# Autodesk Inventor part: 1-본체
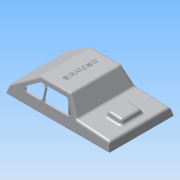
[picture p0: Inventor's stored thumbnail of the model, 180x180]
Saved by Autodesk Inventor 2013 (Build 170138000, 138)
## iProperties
Created: 2015-05
Part Number: 1-본체
Material: ABS 플라스틱
Document SubType Name: Modeling
Designer: Administrator
Density: 1.06 g/cm^3
Mass: 31.5653 g
Surface Area: 297.913 cm^2
Volume: 29.7786 cm^3
Author: Administrator
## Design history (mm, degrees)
sketch "스케치1"
  geometry: L1 (61, -38)-(-61, -38); L2 (-61, -38)-(-61, 38); L3 (-61, 38)-(61, 38); L4 (61, 38)-(61, -38); L5 (61, -38)-(-61, 38); L6 (-61, -38)-(61, 38); 1 further point
  constraints: 12 end point, 2 midpoint, 2 parallel, 1 horizontal, 1 perpendicular
  dimensions: "d0" = 122 distance of L2.end L3.end; "d2" = 76 distance of L3.end L1.start
extrude "돌출1" new body sketch "스케치1" distance "d3" = 30; taper "d4" = -15 deg
node "작업 평면1"
sketch "스케치3"
  geometry: L1 (52.962, 30)-(-52.962, 30) reference; L2 (-61, 0)-(-52.962, 30) reference; L3 (61, 0)-(-61, 0) reference; L4 (61, 0)-(52.962, 30) reference; L5 (-58.588, 9)-(-19, 11.075); L6 (-19, 11.075)-(-7.174, 30); L7 (28.321, 30)-(58.321, 10); L8 (60.732, 1)-(59.732, 1); L9 (59.732, 1)-(59.732, 0); L10 (-60.732, 1)-(-59.732, 1); L11 (-59.732, 1)-(-59.732, 0); L12 (61, 0)-(52.962, 30) reference; 1 further point
  constraints: 14 end point, 8 point on line, 3 perpendicular, 1 parallel
  dimensions: "d23" = 9 distance from line of L3 L5.start; "d25" = 125 deg angle of L6 L5; "d27" = 1 distance of L10.start L10.end; "d28" = 1 distance of L10.end L11.end; "d29" = 1 distance of L8.start L8.end; "d30" = 1 distance of L8.end L9.end; "d31" = 30 horizontal distance of L7.start L7.end; "d32" = 20 vertical distance of L7.start L7.end; "d34" = 3 deg angle of L3 L5; "d83" = 42 horizontal distance of L5.end L2.start
extrude "돌출3" cut sketch "스케치3" stored distance "d35" = 31; taper "d36" = 0 deg
sketch "스케치5"
  geometry: L1 (-8.121, 22.588)-(-28.121, 22.588); L2 (-28.121, 22.588)-(-28.121, 48.588); L3 (-28.121, 48.588)-(-8.121, 48.588); L4 (-8.121, 48.588)-(-8.121, 22.588); L5 (-8.121, 22.588)-(-28.121, 48.588); L6 (-28.121, 22.588)-(-8.121, 48.588); L7 (2.879, 73.588)-(2.879, -2.412) reference; 3 further points
  constraints: 12 end point, 3 midpoint, 2 parallel, 1 horizontal, 1 horizontal alignment, 1 perpendicular
  dimensions: "d37" = 20 distance of L2.end L3.end; "d40" = 26 distance of L1.end L2.end; "d65" = 11 distance between parallel lines of L7 L4
extrude "돌출4" join sketch "스케치5" distance "d42" = 5; taper "d43" = -20 deg
feature "쉘1" dims "d44" = 2
sketch "스케치6"
  geometry: L1 (-4.403, 25)-(-10.908, 14.59); L2 (-8.364, 10)-(17.224, 10); L3 (20.224, 13)-(20.224, 22); L4 (17.224, 25)-(-4.403, 25); L5 (61, 0)-(58.321, 10) reference; L6 (58.321, 10)-(28.321, 30) reference; L7 (28.321, 30)-(-7.174, 30) reference; L8 (-7.174, 30)-(-19, 11.075) reference; L9 (-19, 11.075)-(-58.588, 9) reference; L10 (-61, 0)-(-58.588, 9) reference; L11 (61, 0)-(-61, 0) reference; L12 (-7.174, 30)-(-19, 11.075) reference; L13 (58.321, 10)-(28.321, 30) reference; L14 (21.307, 22)-(21.307, 13); L15 (24.307, 10)-(39.398, 10); L16 (41.062, 15.496)-(26.807, 25); L17 (26.807, 25)-(24.307, 25); A1 r 3 centre (39.398, 13) between (39.398, 10) and (41.062, 15.496); A2 r 3 centre (24.307, 22) between (24.307, 25) and (21.307, 22); A3 r 3 centre (24.307, 13) between (21.307, 13) and (24.307, 10); A4 r 3 centre (17.224, 22) between (20.224, 22) and (17.224, 25); A5 r 3 centre (17.224, 13) between (17.224, 10) and (20.224, 13); A6 r 3 centre (-8.364, 13) between (-10.908, 14.59) and (-8.364, 10); 6 further points
  constraints: 16 end point, 12 point on circle, 12 tangent, 10 point on line, 6 centre point, 4 equal radius, 4 perpendicular, 3 parallel, 2 collinear, 1 horizontal
  dimensions: "d46" = 34 distance of point (-13.776, 10) point (20.224, 10); "d48" = 15 vertical distance of L1.start point (-13.776, 10); "d54" = 5 distance between parallel lines of L8 L1; "d56" = 5 distance between parallel lines of L4 L7; "d79" = 5 distance between parallel lines of L6 L16; "d80" = 28 distance of point (21.307, 10) point (49.307, 10); "d81" = 3 radius of A1; "d82" = 3 radius of A2
extrude "돌출5" cut sketch "스케치6" stored distance "d57" = 5; taper "d58" = 0 deg
sketch "스케치10"
  geometry: L1 (61, -38)-(61, 38) reference; L2 (61, 38)-(-61, 38) reference; L3 (-61, 38)-(-61, -38) reference; L4 (-60, -37)-(-60, 37); L5 (-60, 37)-(60, 37); L6 (60, 37)-(60, -37); L7 (-60, -37)-(60, -37); L8 (-61, -38)-(61, -38) reference; 1 further point
  constraints: 8 end point, 1 perpendicular
  dimensions: "d66" = 1 distance between parallel lines of L2 L5; "d67" = 1 distance between parallel lines of L8 L7; "d68" = 1 distance between parallel lines of L4 L3; "d69" = 1 distance between parallel lines of L1 L6
extrude "돌출6" join sketch "스케치10" distance "d70" = 1; taper "d71" = 0 deg
sketch "스케치11"
  geometry: L1 (-60, 37)-(-60, -37) reference; L2 (-60, -37)-(60, -37) reference; L3 (60, -37)-(60, 37) reference; L4 (60, 37)-(-60, 37) reference; L5 (-59, 36)-(-59, -36); L6 (-59, -36)-(59, -36); L7 (59, -36)-(59, 36); L8 (59, 36)-(-59, 36); 1 further point
  constraints: 8 end point, 3 other
  dimensions: "d72" = 1 distance between parallel lines of L8 L4
extrude "돌출7" cut sketch "스케치11" distance "d73" = 1; taper "d74" = 0 deg
node "작업 평면2"
sketch "스케치12"
  geometry: L1 (-33.879, -9.78)-(-33.879, 9.78) reference; L2 (-33.879, 9.78)-(-47.42, 9.78) reference; L3 (-47.42, 9.78)-(-47.42, -9.78) reference; L4 (-47.42, -9.78)-(-33.879, -9.78) reference; C1 r 3 at (-40.65, 0); C2 r 3 at (-0.65, -22); C3 r 3 at (-0.65, 22); C4 r 3 at (39.35, 0); 3 further points
  constraints: 4 centre point, 3 equal radius, 2 horizontal alignment, 2 midpoint, 2 vertical alignment
  dimensions: "d85" = 40 horizontal distance of C3.centre C1.centre; "d87" = 40 horizontal distance of C4.centre C3.centre; "d89" = 6 diameter of C4; "d90" = 22 vertical distance of point (0, 0) C3.centre; "d91" = 22 vertical distance of point (0, 0) C2.centre
extrude "돌출8" join sketch "스케치12" stored distance "d92" = 1; taper "d93" = 0 deg
sketch "스케치15"
  geometry: L1 (-61, -38)-(-61, 38) reference; 2 further points
  constraints: 1 horizontal alignment, 1 other
  dimensions: "d103" = 50 distance from line of L1 point (-11, 0)
feature "엠보싱1" sketch "스케치15" dims "d0" = 122, "d2" = 76, "d104" = 0.5, "d105" = 0
fillet "모깎기1" dims "d101" = 3
fillet "모깎기2" dims "d102" = 3
fillet "모깎기4" dims "d107" = 3
fillet "모깎기5" dims "d108" = 3
fillet "모깎기6" dims "d109" = 3
fillet "모깎기7" dims "d110" = 12
fillet "모깎기10" dims "d113" = 3
fillet "모깎기11" dims "d114" = 3
sketch "스케치16"
  geometry: C1 r 3 at (0, 0) reference; C2 r 3 at (-80, 0) reference; C3 r 3 at (-40, 22) reference; C4 r 3 at (-40, -22) reference; 5 further points
  constraints: 4 coincident
hole "구멍1" sketch "스케치16" at (0, 0), (-40, 22), (-40, -22), (-80, 0) diameter "d115" = 3.242; stored, may be unused: countersink angle "d119" = 90 deg, drill point angle "d121" = 118 deg; dims "d116" = 9, "d117" = 4, "d118" = 2, "d120" = 11
node "솔리드1"
node "투영된 루프1"
node "투영된 루프2"
node "투영된 루프8"
node "투영된 루프15"
node "투영된 루프16"
node "투영된 루프17"
other parameters: "d22" = 0, "d84" = -1
